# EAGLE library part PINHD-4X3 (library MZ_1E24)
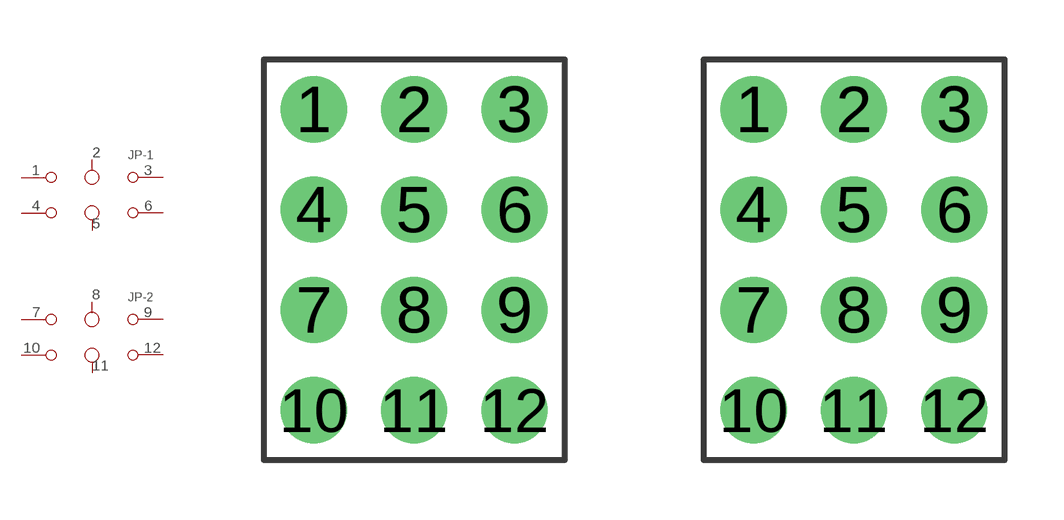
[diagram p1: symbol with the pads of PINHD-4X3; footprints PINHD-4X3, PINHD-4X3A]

Designator prefix JP; gates -1=PINHD-2X3 -2=PINHD-2X3

## PINHD-4X3  [PINHD-4X3]
1  -1:1  pas
2  -1:2  pas
3  -1:3  pas
4  -1:4  pas
5  -1:5  pas
6  -1:6  pas
7  -2:1  pas
8  -2:2  pas
9  -2:3  pas
10  -2:4  pas
11  -2:5  pas
12  -2:6  pas

## PINHD-4X3A  [PINHD-4X3A]
Pads as for PINHD-4X3

## PINHD-4X3B  [PINHD-4X3B]
Pads as for PINHD-4X3

## Footprint PINHD-4X3 (pad centres in mm)
drill 1.016 pad 1.676 round: 1 -2.54,3.81; 2 0,3.81; 3 2.54,3.81; 4 -2.54,1.27; 5 0,1.27; 6 2.54,1.27; 7 -2.54,-1.27; 8 0,-1.27; 9 2.54,-1.27; 10 -2.54,-3.81; 11 0,-3.81; 12 2.54,-3.81

## Footprint PINHD-4X3A (pad centres in mm)
drill 1.016 pad 1.676 round: 1 -2.54,3.81; 2 0,3.81; 3 2.54,3.81; 4 -2.54,1.27; 5 0,1.27; 6 2.54,1.27; 7 -2.54,-1.27; 8 0,-1.27; 9 2.54,-1.27; 10 -2.54,-3.81; 11 0,-3.81; 12 2.54,-3.81

## Footprint PINHD-4X3B (pad centres in mm)
drill 1.016 pad 1.676 round: 1 -2.54,3.81; 2 0,3.81; 3 2.54,3.81; 4 -2.54,1.27; 5 0,1.27; 6 2.54,1.27; 7 -2.54,-1.27; 8 0,-1.27; 9 2.54,-1.27; 10 -2.54,-3.81; 11 0,-3.81; 12 2.54,-3.81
